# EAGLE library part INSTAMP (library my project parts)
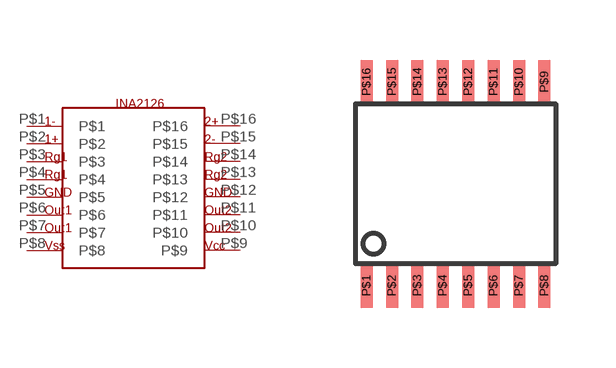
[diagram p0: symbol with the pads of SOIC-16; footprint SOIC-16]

Designator prefix -

## INSTAMP  [SOIC-16]
P$1  P$1
P$2  P$2
P$3  P$3
P$4  P$4
P$5  P$5
P$6  P$6
P$7  P$7
P$8  P$8
P$9  P$9
P$10  P$10
P$11  P$11
P$12  P$12
P$13  P$13
P$14  P$14
P$15  P$15
P$16  P$16

## Footprint SOIC-16 (pad centres in mm)
smd 0.3 x 1.1: P$1 -2.223,-2.55; P$2 -1.587,-2.55; P$3 -0.953,-2.55; P$4 -0.318,-2.55; P$5 0.318,-2.55; P$6 0.953,-2.55; P$7 1.587,-2.55; P$8 2.223,-2.55; P$9 2.223,2.55; P$10 1.587,2.55; P$11 0.953,2.55; P$12 0.318,2.55; P$13 -0.318,2.55; P$14 -0.953,2.55; P$15 -1.587,2.55; P$16 -2.223,2.55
